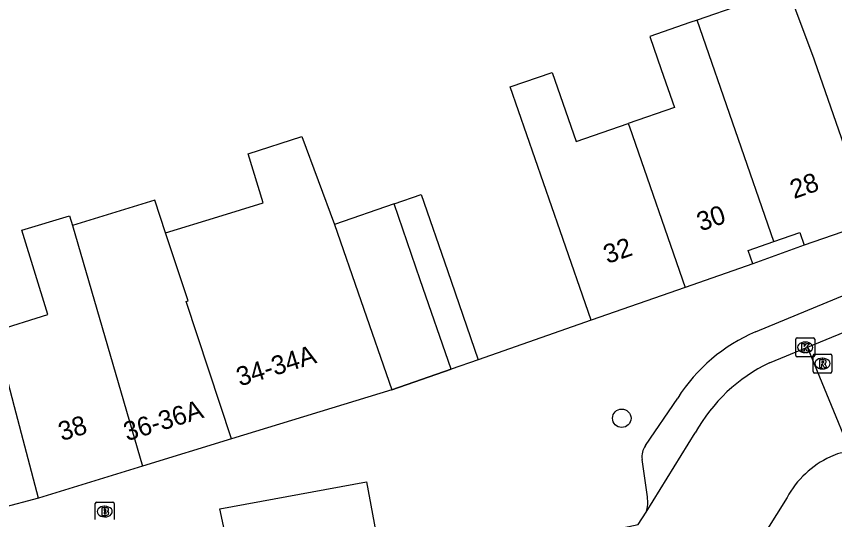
# Model space of a CAD drawing. Extents: x 159377 to 159983, y 382996 to 383595.
# Drawn here: x 159804.52 to 159847.85, y 383343.33 to 383369.96 of the extents above; entities that cross this region are included whole.
import ezdxf

# ---------------------------------------------------------------- set-up
doc = ezdxf.new("R2010")
doc.units = 0
for name, color, linetype in [('IMGEO_Boom', 7, 'Continuous'), ('IMGEO_Brandkraan', 7, 'Continuous'), ('IMGEO_Kolk', 7, 'Continuous'), ('IMGEO_Pand', 7, 'Continuous'), ('IMGEO_Pand_nummerreeks', 7, 'Continuous'), ('IMGEO_Pand_overbouw', 7, 'Continuous'), ('IMGEO_Rijbaan_lokaal_open', 7, 'Continuous'), ('IMGEO_Rioolput', 7, 'Continuous'), ('IMGEO_Voetpad_open', 7, 'Continuous')]:
    doc.layers.add(name, color=color, linetype=linetype)

msp = doc.modelspace()

# ---------------------------------------------------------------- linework, layer by layer
at = {"layer": 'IMGEO_Boom'}
msp.add_circle((159836.581, 383348.692), 0.489, dxfattribs=at)
at = {"layer": 'IMGEO_Brandkraan'}
for p, q in [((159808.7, 383343.327), (159808.7, 383344.179)), ((159808.775, 383344.253), (159809.627, 383344.253)), ((159809.701, 383344.179), (159809.701, 383343.327)), ((159809.188, 383344.033), (159809.213, 383344.033)), ((159809.211, 383343.473), (159809.186, 383343.473))]:
    msp.add_line(p, q, dxfattribs=at)
for points in [[(159808.7, 383343.327), (159808.7, 383344.179)], [(159808.775, 383344.253), (159809.627, 383344.253)], [(159809.701, 383344.179), (159809.701, 383343.327)], [(159809.048, 383343.953), (159809.048, 383343.553), (159809.261, 383343.553)], [(159809.279, 383343.953), (159809.048, 383343.953)], [(159809.227, 383343.872), (159809.173, 383343.872), (159809.173, 383343.796)], [(159809.173, 383343.796), (159809.226, 383343.796)], [(159809.235, 383343.72), (159809.173, 383343.72), (159809.173, 383343.639)], [(159809.173, 383343.639), (159809.235, 383343.639)]]:
    msp.add_lwpolyline(points, dxfattribs=at)
for centre, radius, start, end in [((159808.777, 383344.177), 0.0765, 91.552, 178.448), ((159808.777, 383344.177), 0.0765, 91.552, 178.448), ((159809.625, 383344.177), 0.0765, 1.552, 88.448), ((159809.625, 383344.177), 0.0765, 1.552, 88.448), ((159809.228, 383343.834), 0.0379, 267.8285, 90.9355), ((159809.283, 383343.808), 0.145, 59.4692, 91.5367), ((159809.308, 383343.855), 0.0922, 285.5137, 58.1501), ((159809.313, 383343.663), 0.105, 301.3115, 78.989), ((159809.236, 383343.679), 0.0404, 269.8759, 90.5077), ((159809.267, 383343.804), 0.251, 268.6676, 293.5347)]:
    msp.add_arc(centre, radius, start, end, dxfattribs=at)
for centre, major_axis, ratio, start_param, end_param in [((159809.187, 383343.753), (-0.387, 0.002), 0.722429, 4.712389, 7.853982), ((159809.212, 383343.753), (-0.39, 0.002), 0.717154, 1.570796, 4.712389)]:
    msp.add_ellipse(centre, major_axis=major_axis, ratio=ratio, start_param=start_param, end_param=end_param, dxfattribs=at)
at = {"layer": 'IMGEO_Kolk'}
for p, q in [((159845.796, 383352.017), (159845.796, 383352.869)), ((159845.871, 383352.943), (159846.723, 383352.943)), ((159846.797, 383352.869), (159846.797, 383352.017)), ((159846.284, 383352.723), (159846.309, 383352.723)), ((159846.307, 383352.163), (159846.282, 383352.163)), ((159846.723, 383351.943), (159845.871, 383351.943))]:
    msp.add_line(p, q, dxfattribs=at)
for points in [[(159845.796, 383352.017), (159845.796, 383352.869)], [(159845.871, 383352.943), (159846.723, 383352.943)], [(159846.797, 383352.869), (159846.797, 383352.017)], [(159846.117, 383352.643), (159846.24, 383352.643), (159846.24, 383352.492), (159846.37, 383352.643), (159846.534, 383352.643), (159846.388, 383352.492), (159846.541, 383352.243), (159846.389, 383352.243), (159846.304, 383352.407), (159846.24, 383352.34), (159846.24, 383352.243), (159846.117, 383352.243), (159846.117, 383352.643)], [(159846.723, 383351.943), (159845.871, 383351.943)]]:
    msp.add_lwpolyline(points, dxfattribs=at)
for centre, start, end in [((159845.873, 383352.867), 91.552, 178.448), ((159845.873, 383352.867), 91.552, 178.448), ((159846.721, 383352.867), 1.552, 88.448), ((159846.721, 383352.867), 1.552, 88.448), ((159845.873, 383352.019), 181.552, 268.448), ((159845.873, 383352.019), 181.552, 268.448), ((159846.721, 383352.019), 271.552, 358.448), ((159846.721, 383352.019), 271.552, 358.448)]:
    msp.add_arc(centre, 0.0765, start, end, dxfattribs=at)
for centre, major_axis, ratio, start_param, end_param in [((159846.283, 383352.443), (-0.387, 0.002), 0.722429, 4.712389, 7.853982), ((159846.308, 383352.443), (-0.39, 0.002), 0.717154, 1.570796, 4.712389)]:
    msp.add_ellipse(centre, major_axis=major_axis, ratio=ratio, start_param=start_param, end_param=end_param, dxfattribs=at)
at = {"layer": 'IMGEO_Pand'}
for points in [[(159845.368, 383371.426), (159842.919, 383370.575), (159840.573, 383369.76)], [(159849.765, 383359.071), (159846.807, 383367.595), (159846.769, 383367.697), (159845.368, 383371.426)], [(159840.573, 383369.76), (159840.192, 383369.628), (159838.064, 383368.889), (159838.672, 383367.139), (159839.366, 383365.141), (159836.92, 383364.291)], [(159844.638, 383358.043), (159840.573, 383369.76)], [(159834.964, 383353.885), (159833.323, 383358.609), (159830.679, 383366.223), (159832.9, 383366.995), (159834.17, 383363.336), (159836.92, 383364.291)], [(159836.92, 383364.291), (159836.985, 383364.113), (159839.937, 383355.612)], [(159812.416, 383358.501), (159815.196, 383359.353), (159817.593, 383360.088), (159816.794, 383362.69), (159819.647, 383363.593), (159821.367, 383358.941), (159822.759, 383354.928), (159824.398, 383350.204)], [(159812.416, 383358.501), (159811.848, 383360.226), (159807.49, 383358.888)], [(159827.543, 383351.29), (159825.913, 383356.017), (159824.528, 383360.031), (159825.961, 383360.526), (159827.347, 383356.514), (159828.979, 383351.787)], [(159805.695, 383344.463), (159804.418, 383349.298), (159803.359, 383353.307), (159806.187, 383354.175), (159804.817, 383358.638), (159807.33, 383359.41), (159807.49, 383358.888)], [(159849.765, 383359.071), (159846.235, 383357.845)], [(159807.49, 383358.888), (159811.206, 383346.155)], [(159815.921, 383347.602), (159813.518, 383354.874), (159813.623, 383354.911), (159813.479, 383355.326), (159812.416, 383358.501)], [(159844.638, 383358.043), (159846.002, 383358.517), (159846.235, 383357.845)], [(159843.522, 383356.857), (159843.274, 383357.57), (159844.638, 383358.043)], [(159843.522, 383356.857), (159839.937, 383355.612)], [(159839.937, 383355.612), (159834.964, 383353.885)], [(159828.979, 383351.787), (159827.543, 383351.29)], [(159824.398, 383350.204), (159815.921, 383347.602)], [(159815.921, 383347.602), (159811.206, 383346.155)], [(159811.206, 383346.155), (159805.695, 383344.463)]]:
    msp.add_lwpolyline(points, dxfattribs=at)
at = {"layer": 'IMGEO_Pand_overbouw'}
msp.add_lwpolyline([(159824.528, 383360.031), (159821.367, 383358.941), (159822.759, 383354.928), (159824.398, 383350.204), (159827.543, 383351.29), (159825.913, 383356.017)], close=True, dxfattribs=at)
at = {"layer": 'IMGEO_Rijbaan_lokaal_open'}
for points in [[(159846.413, 383352.453), (159852.647, 383355.016)], [(159844.401, 383351.626), (159846.413, 383352.453)], [(159848.705, 383346.88), (159846.413, 383352.453)], [(159837.878, 383343.725), (159840.476, 383347.927)], [(159845.336, 383344.495), (159843.551, 383341.665)], [(159835.044, 383342.564), (159837.443, 383343.072), (159837.878, 383343.725)]]:
    msp.add_lwpolyline(points, dxfattribs=at)
for centre, radius, start, end in [((159848.26, 383343.6), 8.906, 115.6761, 150.9281), ((159848.566, 383344.927), 1.957, 85.9289, 118.6668), ((159849.668, 383342.175), 4.914, 114.5374, 151.8256)]:
    msp.add_arc(centre, radius, start, end, dxfattribs=at)
at = {"layer": 'IMGEO_Rioolput'}
for p, q in [((159846.709, 383351.158), (159846.709, 383352.01)), ((159846.784, 383352.084), (159847.636, 383352.084)), ((159847.71, 383352.01), (159847.71, 383351.158)), ((159847.197, 383351.864), (159847.222, 383351.864)), ((159847.22, 383351.304), (159847.195, 383351.304)), ((159847.636, 383351.084), (159846.784, 383351.084))]:
    msp.add_line(p, q, dxfattribs=at)
for points in [[(159846.709, 383351.158), (159846.709, 383352.01)], [(159846.784, 383352.084), (159847.636, 383352.084)], [(159847.71, 383352.01), (159847.71, 383351.158)], [(159847.298, 383351.782), (159847.046, 383351.784), (159847.046, 383351.384)], [(159847.046, 383351.384), (159847.17, 383351.384), (159847.17, 383351.546), (159847.181, 383351.546)], [(159847.224, 383351.703), (159847.17, 383351.703), (159847.17, 383351.622)], [(159847.17, 383351.622), (159847.222, 383351.622)], [(159847.228, 383351.517), (159847.299, 383351.384), (159847.439, 383351.384), (159847.374, 383351.51)], [(159847.636, 383351.084), (159846.784, 383351.084)]]:
    msp.add_lwpolyline(points, dxfattribs=at)
for centre, radius, start, end in [((159846.786, 383352.008), 0.0765, 91.552, 178.448), ((159846.786, 383352.008), 0.0765, 91.552, 178.448), ((159847.634, 383352.008), 0.0765, 1.552, 88.448), ((159847.634, 383352.008), 0.0765, 1.552, 88.448), ((159847.18, 383351.493), 0.0533, 26.0293, 88.6989), ((159847.206, 383351.811), 0.19, 274.7715, 282.9687), ((159847.23, 383351.607), 0.0964, 77.0061, 93.1865), ((159847.244, 383351.664), 0.0378, 276.6634, 79.6772), ((159847.297, 383351.672), 0.109, 350.3612, 89.416), ((159847.295, 383351.672), 0.112, 277.5842, 350.9817), ((159847.279, 383351.457), 0.108, 29.5134, 73.7905), ((159846.786, 383351.16), 0.0765, 181.552, 268.448), ((159846.786, 383351.16), 0.0765, 181.552, 268.448), ((159847.634, 383351.16), 0.0765, 271.552, 358.448), ((159847.634, 383351.16), 0.0765, 271.552, 358.448)]:
    msp.add_arc(centre, radius, start, end, dxfattribs=at)
for centre, major_axis, ratio, start_param, end_param in [((159847.196, 383351.584), (-0.387, 0.002), 0.722429, 4.712389, 7.853982), ((159847.221, 383351.584), (-0.39, 0.002), 0.717154, 1.570796, 4.712389)]:
    msp.add_ellipse(centre, major_axis=major_axis, ratio=ratio, start_param=start_param, end_param=end_param, dxfattribs=at)
at = {"layer": 'IMGEO_Voetpad_open'}
for points in [[(159843.667, 383353.269), (159867.764, 383363.229), (159868.256, 383363.221), (159868.544, 383363.141), (159869.447, 383362.64)], [(159846.235, 383357.845), (159843.522, 383356.857)], [(159834.964, 383353.885), (159828.979, 383351.787)], [(159827.543, 383351.29), (159824.398, 383350.204)], [(159837.844, 383347.252), (159839.543, 383349.76)], [(159837.935, 383344.527), (159837.662, 383346.509)], [(159815.75, 383341.756), (159815.295, 383343.9), (159823.056, 383345.322), (159823.779, 383341.426)], [(159805.695, 383344.463), (159803.704, 383343.932)]]:
    msp.add_lwpolyline(points, dxfattribs=at)
for centre, radius, start, end in [((159847.3, 383344.821), 9.196, 113.2721, 147.515), ((159838.635, 383346.664), 0.986, 143.4, 189.0725), ((159836.402, 383344.233), 1.561, 341.0116, 10.8578)]:
    msp.add_arc(centre, radius, start, end, dxfattribs=at)

# ---------------------------------------------------------------- texts
at = {"layer": 'IMGEO_Pand_nummerreeks'}
for s, rotation, p in [('28', 19.1769, (159845.702, 383360.288)), ('30', 19.1769, (159840.764, 383358.571)), ('32', 19.1772, (159835.821, 383356.852)), ('34-34A', 17.0638, (159816.355, 383350.371)), ('36-36A', 17.0627, (159810.377, 383347.47)), ('38', 17.0677, (159806.924, 383347.476))]:
    msp.add_text(s, height=1, rotation=rotation, dxfattribs=at).set_placement(p)

doc.saveas('drawing.dxf')
